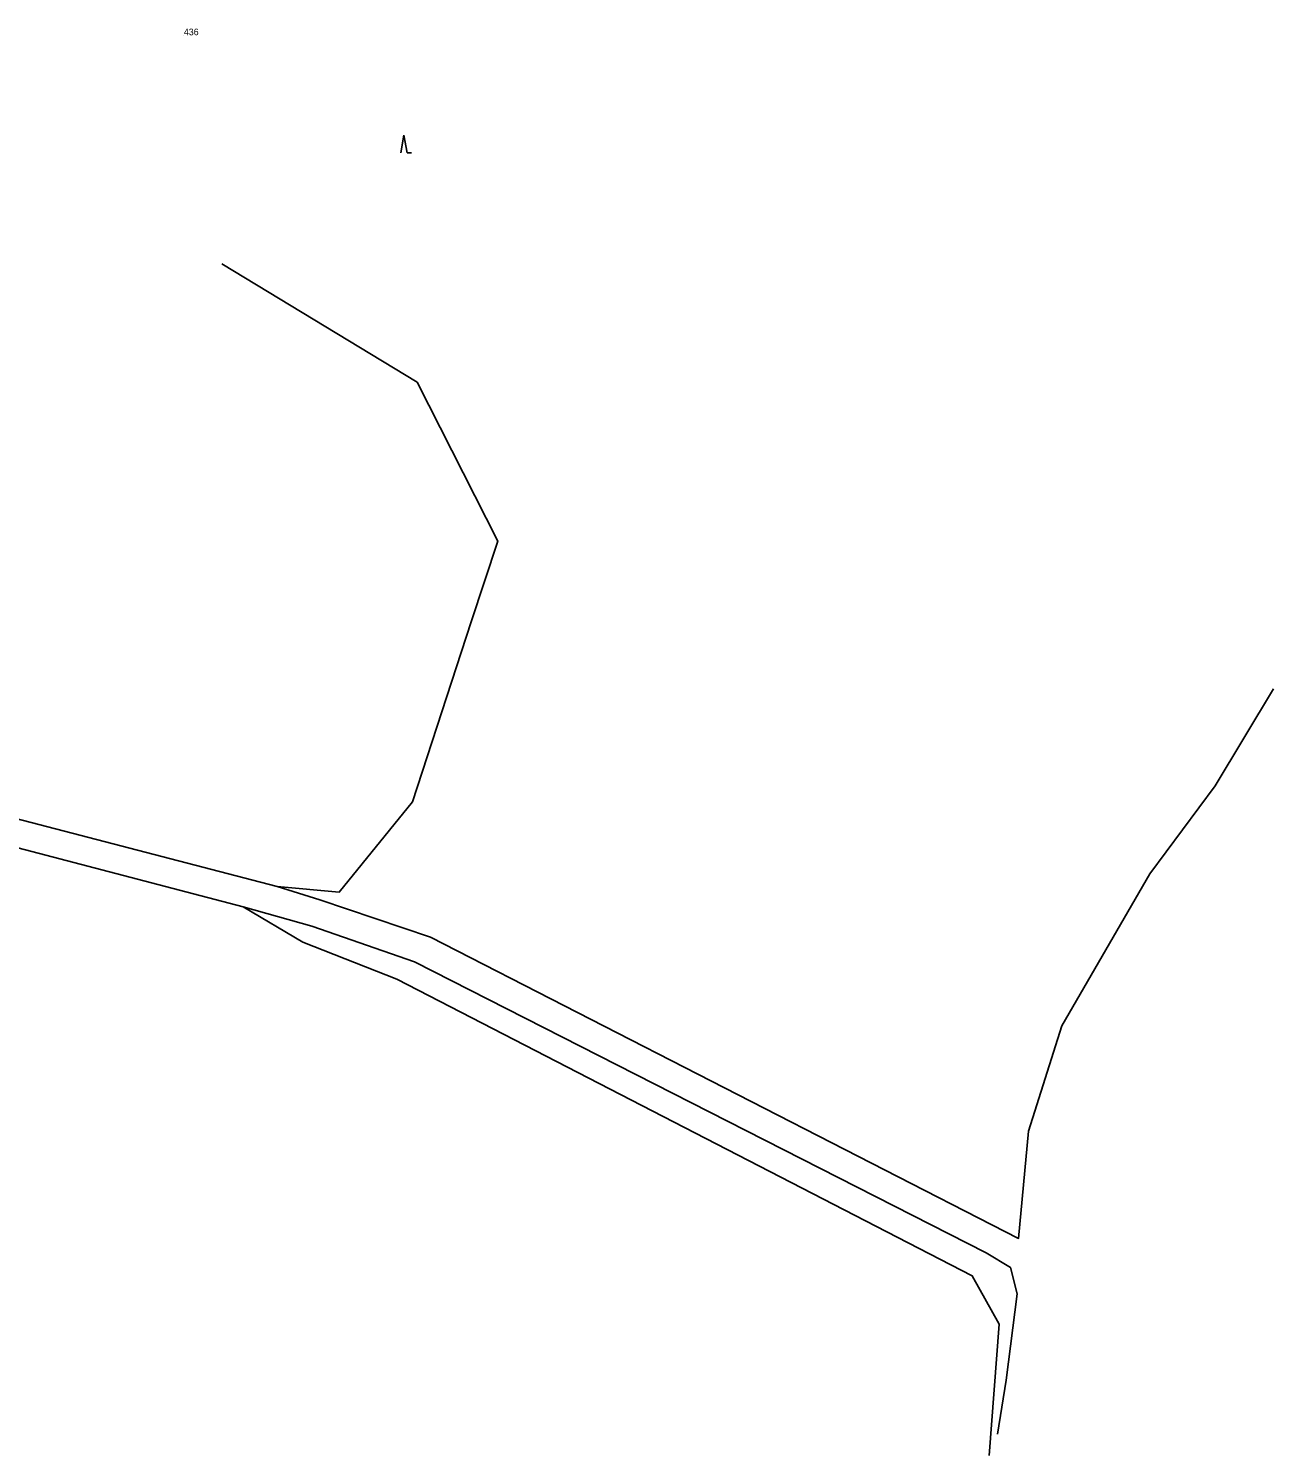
# Model space of a CAD drawing. Extents: x -836568 to -836015, y -1070547 to -1070212.
# Drawn here: x -836156.9 to -836015.2, y -1070546.8 to -1070384.3 of the extents above; entities that cross this region are included whole.
import ezdxf

# ---------------------------------------------------------------- set-up
doc = ezdxf.new("R2010")
doc.units = 0
for name, color, linetype in [('BodPole_mer', 7, 'Continuous'), ('Doprava_hranice', 7, 'Continuous'), ('OstPloch_hranice', 7, 'Continuous'), ('OstPloch_kody', 7, 'Continuous'), ('RuianPar_popis', 7, 'Continuous')]:
    doc.layers.add(name, color=color, linetype=linetype)

msp = doc.modelspace()

# ---------------------------------------------------------------- linework, layer by layer
at = {"layer": 'BodPole_mer'}
for p, q in [((-836134.89, -1070411.1), (-836134.89, -1070411.1)), ((-836112.67, -1070424.6), (-836112.67, -1070424.6)), ((-836128.61, -1070481.99), (-836128.61, -1070481.99)), ((-836132.47, -1070484.33), (-836132.47, -1070484.33)), ((-836125.66, -1070488.35), (-836125.66, -1070488.35))]:
    msp.add_line(p, q, dxfattribs=at)
at = {"layer": 'Doprava_hranice'}
for points in [[(-836015.21, -1070459.49), (-836021.84, -1070470.53), (-836029.29, -1070480.55), (-836039.31, -1070497.89), (-836043.1, -1070509.87), (-836044.22, -1070522.08), (-836111.13, -1070487.77), (-836123.74, -1070483.53), (-836128.61, -1070481.99), (-836211.76, -1070460.38), (-836245.95, -1070449.75), (-836269.46, -1070440.2)], [(-836046.6, -1070544.35), (-836045.64, -1070538.23), (-836044.38, -1070528.39), (-836045.14, -1070525.37), (-836047.92, -1070523.71), (-836112.97, -1070490.6), (-836124.66, -1070486.54), (-836132.47, -1070484.33), (-836212.77, -1070463.28), (-836247.95, -1070452.55), (-836271.41, -1070444.47)]]:
    msp.add_lwpolyline(points, dxfattribs=at)
at = {"layer": 'OstPloch_hranice'}
for points in [[(-836134.89, -1070411.1), (-836112.67, -1070424.6), (-836103.5, -1070442.7), (-836106.5, -1070451.88), (-836113.2, -1070472.38), (-836121.53, -1070482.64), (-836128.61, -1070481.99)], [(-836047.55, -1070546.79), (-836046.42, -1070531.83), (-836049.49, -1070526.32), (-836114.97, -1070492.57), (-836125.66, -1070488.35), (-836132.47, -1070484.33)]]:
    msp.add_lwpolyline(points, dxfattribs=at)
at = {"layer": 'OstPloch_kody'}
for p, q in [((-836114.17, -1070396.46), (-836114.54, -1070398.46)), ((-836114.17, -1070396.46), (-836113.8, -1070398.46)), ((-836113.8, -1070398.46), (-836113.3, -1070398.46))]:
    msp.add_line(p, q, dxfattribs=at)
at = {"layer": 'RuianPar_popis'}
msp.add_line((-836139.21, -1070385.08), (-836139.21, -1070385.08), dxfattribs=at)

# ---------------------------------------------------------------- texts
msp.add_text('436', height=0.75, dxfattribs=at).set_placement((-836139.21, -1070385.08))

doc.saveas('drawing.dxf')
